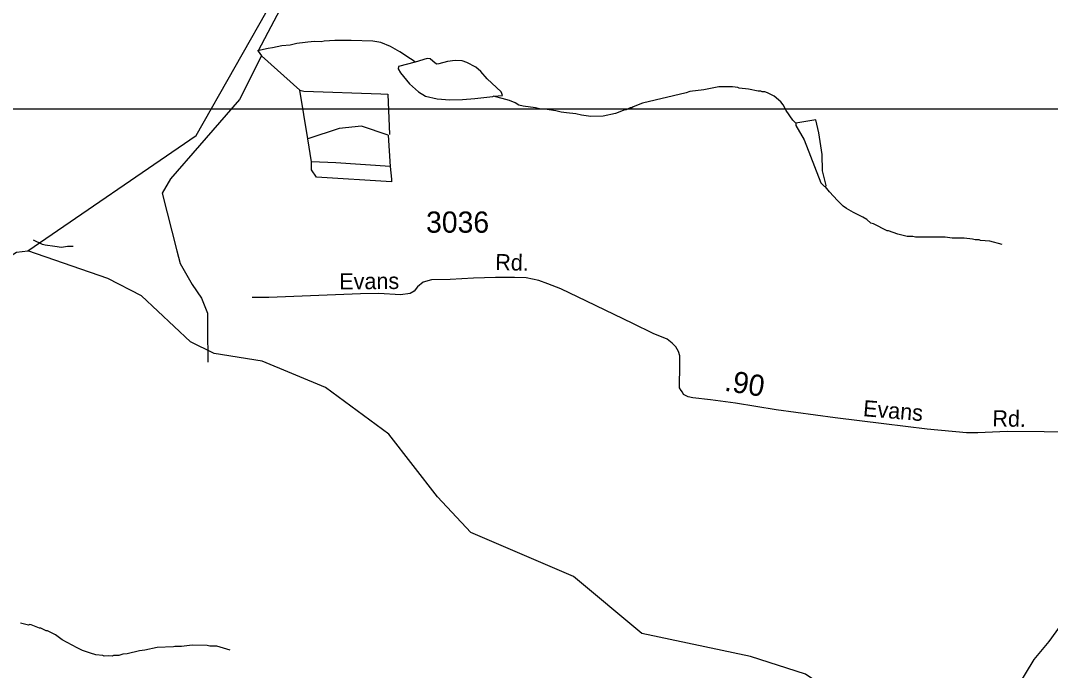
# Model space of a CAD drawing. Extents: x 1547597 to 1699558, y 810033 to 920809.
# Drawn here: x 1609618 to 1615688, y 827999 to 831828 of the extents above; entities that cross this region are included whole.
import ezdxf

# ---------------------------------------------------------------- set-up
doc = ezdxf.new("R2010")
doc.units = 0
for name, color, linetype in [('Exist Hydrographic Creek Single Shore', 7, 'Continuous'), ('Exist Hydrographic Misc Water Feature', 7, 'Continuous'), ('Exist Road Non-System Type 51', 7, 'Continuous'), ('Exist Road Secondary Mileage Hundredths English Label', 7, 'Continuous'), ('Exist Road Secondary Type 51 Attributed', 7, 'Continuous'), ('Exist Road Secondary Type 51 Label', 7, 'Continuous'), ('Exist Road Secondary Type 51 Number Label', 7, 'Continuous'), ('Map Preparation Inset Cut Line', 7, 'Continuous')]:
    doc.layers.add(name, color=color, linetype=linetype)

msp = doc.modelspace()

# ---------------------------------------------------------------- linework, layer by layer
at = {"layer": 'Exist Hydrographic Creek Single Shore'}
for points in [[(1609659.7, 830472.1), (1610651.7, 831151.1), (1611112.7, 831962.5), (1611121.7, 832011.5)], [(1606665.7, 828095.8), (1606891.9, 828225.7), (1607162.7, 828310.2), (1607833.6, 828602.7), (1608128.8, 828653.6), (1608244.3, 828846.1), (1608341, 828973.5), (1608539.5, 829644), (1608748.2, 829893.6), (1609155.7, 830193.4), (1609592.7, 830463.6), (1609659.7, 830472.1)], [(1614418.7, 827857.8), (1614244.7, 827976.2), (1613920.7, 828081.3), (1613280.7, 828215.7), (1612876.7, 828552.1), (1612271.7, 828810.6), (1612074.7, 829021.4), (1611787.7, 829391.6), (1611415.7, 829665), (1611042.6, 829820.4), (1610759.7, 829865.5), (1610619.7, 829934), (1610330.7, 830205.7), (1610132.7, 830308.2), (1609659.7, 830472.1)]]:
    msp.add_lwpolyline(points, dxfattribs=at)
at = {"layer": 'Exist Hydrographic Misc Water Feature'}
for points in [[(1611944.4, 831583), (1611932.6, 831592.1), (1611916.7, 831602.3), (1611853.3, 831643.2), (1611797.8, 831676), (1611742.1, 831698.7), (1611694.3, 831707.4), (1611566.5, 831711.2), (1611470.5, 831710.5), (1611406.4, 831707.4), (1611390.4, 831703.6), (1611350.4, 831704.2), (1611310.4, 831700.7), (1611294.3, 831698.9), (1611246.4, 831693.7), (1611206.2, 831682.2), (1611158.2, 831678.8), (1611102.1, 831667.7), (1611078, 831664), (1611015.1, 831649.2)], [(1611944.4, 831583), (1611845.6, 831557.3), (1611843.9, 831542.8), (1611856.5, 831521), (1611909.6, 831455.3), (1611962.9, 831408.8), (1612004.4, 831383.5), (1612074.2, 831367.4), (1612147.4, 831361), (1612222.8, 831362.6), (1612295.9, 831368.1), (1612401.6, 831381.2), (1612405.9, 831381.6)], [(1612405.9, 831381.6), (1612457.6, 831386.4), (1612455, 831397.8), (1612449.8, 831408.2), (1612368.7, 831484.7), (1612331.4, 831527.7), (1612300.3, 831552.9), (1612248.5, 831580.9), (1612220.4, 831590.1), (1612179.5, 831592.1), (1612133.6, 831587.8), (1612082.9, 831573.1), (1612070.9, 831571), (1612061.1, 831576.6), (1612031.7, 831603.4), (1612014.9, 831603.6), (1611944.4, 831583)], [(1614187.7, 831224.4), (1614170.4, 831241), (1614131.2, 831297.5), (1614113.7, 831331.7), (1614100, 831349.9), (1614060.5, 831382.4), (1614020.7, 831403), (1614004.8, 831407.3), (1613988.8, 831407.5), (1613980.9, 831411.6), (1613964.9, 831411.8), (1613909.1, 831424.6), (1613853.2, 831429.3), (1613845.3, 831433.4), (1613813.3, 831437.9), (1613733.3, 831437), (1613645.2, 831420.2), (1613563.1, 831409.4), (1613541, 831401.7), (1613284.4, 831341.3), (1613228.1, 831320.1), (1613220, 831314.2), (1613212, 831314.3), (1613187.9, 831302.6), (1613179.9, 831302.8), (1613123.6, 831279.6), (1613051.4, 831264.5), (1612979.5, 831263.6), (1612923.6, 831270.3), (1612891.7, 831278.8), (1612835.8, 831283.6), (1612803.9, 831288), (1612772.1, 831296.5), (1612708.2, 831305.3), (1612684.2, 831305.6), (1612652.3, 831314.1), (1612580.5, 831323.1), (1612555.1, 831330.5), (1612532.4, 831342.5), (1612499.5, 831357.7), (1612405.9, 831381.6)], [(1614362.3, 830848.6), (1614366, 830855.6), (1614345.4, 830942.6), (1614341.9, 831039.3), (1614322.6, 831166), (1614305.3, 831243), (1614187.7, 831224.4)], [(1614187.7, 831224.4), (1614188.5, 831209.1), (1614236.3, 831125.5), (1614335.6, 830871.3), (1614354.3, 830851.3), (1614362.3, 830848.6)], [(1615403.7, 830507.9), (1615332, 830528.9), (1615276.2, 830531.7), (1615268.2, 830535.8), (1615244.2, 830536.1), (1615228.3, 830540.3), (1615180.4, 830545), (1615108.4, 830546), (1615068.5, 830552.6), (1614892.6, 830551.1), (1614876.7, 830555.3), (1614844.7, 830555.7), (1614788.9, 830568.5), (1614733.3, 830589.2), (1614725.3, 830589.4), (1614645.8, 830630.5), (1614629.9, 830634.7), (1614606.2, 830655), (1614582.4, 830669.3), (1614526.8, 830696.1), (1614487.2, 830720.6), (1614467.3, 830734.9), (1614433.8, 830767.4), (1614386.5, 830818.6), (1614362.3, 830848.6)], [(1609928, 830497.2), (1609894, 830496.8), (1609858.8, 830491.3), (1609818.8, 830495.8), (1609763, 830504.6), (1609747, 830508.8), (1609694, 830533.9)], [(1610853.8, 828118), (1610774.1, 828141.1), (1610734.1, 828141.6), (1610718.3, 828145.8), (1610628.3, 828147.1), (1610566.2, 828140), (1610526.2, 828140.5), (1610518.2, 828136.6), (1610422.3, 828134), (1610350.1, 828117), (1610318, 828113.5), (1610245.8, 828096.4), (1610219.9, 828094.8), (1610197.7, 828087.1), (1610165.7, 828085.6), (1610157.6, 828081.7), (1610133.8, 828084), (1610109.8, 828082.3), (1610101.8, 828086.4), (1610061.9, 828091), (1610030, 828099.5), (1609982.2, 828116.1), (1609950.5, 828132.6), (1609863.2, 828179.7), (1609823.6, 828208.3), (1609775.9, 828230.9), (1609767.9, 828231), (1609736.2, 828247.5), (1609728.2, 828247.6), (1609680.5, 828266.3), (1609672.5, 828268.4), (1609664.5, 828264.5), (1609616.7, 828277.2)]]:
    msp.add_lwpolyline(points, dxfattribs=at)
at = {"layer": 'Exist Road Non-System Type 51'}
for points in [[(1611018.5, 831647.4), (1611077.3, 831759.8), (1611165.4, 831926.7), (1611263.9, 832063.2), (1611333.4, 832186.3), (1611388.8, 832303.4), (1611466.8, 832458.4), (1611526.4, 832585.6), (1611590, 832710.6), (1611630.5, 832781.4)], [(1611037, 831619.9), (1610907.3, 831363), (1610672.7, 831092.3), (1610501.5, 830896.1), (1610451.8, 830810.5)], [(1611018.5, 831647.4), (1611037, 831619.9)], [(1611037, 831619.9), (1611263.3, 831418.2), (1611288.2, 831412.7)], [(1611310.3, 831130.9), (1611263.3, 831418.2)], [(1611288.2, 831412.7), (1611740.9, 831396.1), (1611782.3, 831393.4)], [(1611782.3, 831393.4), (1611793.3, 831155.8)], [(1611785, 831153), (1611627.7, 831205.5), (1611495.2, 831191.7), (1611310.3, 831130.9)], [(1611332.3, 830995.6), (1611310.3, 831130.9)], [(1611785, 831153), (1611796.1, 830968)], [(1611796.1, 830968), (1611475.9, 830990.1), (1611332.3, 830995.6)], [(1611362.7, 830904.4), (1611332.3, 830948.6), (1611332.3, 830995.6)], [(1611796.1, 830968), (1611804.3, 830893.4), (1611804.3, 830876.8)], [(1611804.3, 830876.8), (1611362.7, 830904.4)], [(1610451.8, 830810.5), (1610538.1, 830471.8), (1610557.4, 830397.2), (1610629.2, 830272.9), (1610684.4, 830192.8), (1610720.3, 830104.4), (1610720.3, 830016)], [(1611621.1, 830216.8), (1611081.9, 830196.5), (1610981.8, 830195.7)], [(1610720.3, 830016), (1610720.7, 829815.9)]]:
    msp.add_lwpolyline(points, dxfattribs=at)
at = {"layer": 'Exist Road Secondary Type 51 Attributed'}
for points in [[(1615875.1, 829402.9), (1615651.8, 829403.9), (1615433.7, 829406), (1615261.1, 829397.7), (1615193.2, 829399.3), (1614962.3, 829419.3), (1614705.6, 829450.7), (1614420.2, 829486.1), (1614072.3, 829533.4), (1613832.1, 829572.9), (1613684.4, 829593), (1613580.1, 829605.8), (1613553.6, 829611.5), (1613526.4, 829624.3), (1613519.7, 829638.2), (1613511, 829648.5), (1613502.8, 829664.4), (1613501.2, 829696.8), (1613504.3, 829770.3), (1613503.5, 829852), (1613495.3, 829878.7), (1613479.4, 829905.4), (1613458.3, 829928), (1613430.1, 829950.6), (1613345.7, 829983.4), (1613226.8, 830043.6), (1612953.7, 830173.6), (1612801.9, 830247.1), (1612725.6, 830276.9), (1612673.2, 830295.4), (1612598.2, 830311.3), (1612528.8, 830314.9), (1612418.1, 830314.4), (1612287.1, 830310.3), (1612150.1, 830302.6), (1612040.2, 830299.5), (1611991.1, 830286.6), (1611957.2, 830258.9), (1611938.7, 830233.2), (1611915.1, 830218.8), (1611856.5, 830212.7), (1611729, 830218.8), (1611621.1, 830216.8)], [(1615872.1, 828613.9), (1615854.5, 828536.3), (1615829.8, 828455.1), (1615794.5, 828359.8), (1615745.1, 828261), (1615678.1, 828169.2), (1615589.9, 828063.3), (1615494.7, 827904.5), (1615427.7, 827798.6), (1615367.7, 827696.2), (1615311.3, 827618.6), (1615247.8, 827540.9), (1615180.8, 827445.6), (1615022.9, 827216.6), (1614915.3, 827052.5)]]:
    msp.add_lwpolyline(points, dxfattribs=at)
at = {"layer": 'Map Preparation Inset Cut Line'}
for points in [[(1633724, 874749.3), (1571208, 874749.3), (1571208, 831307.2), (1633724, 831307.2)], [(1575502.6, 831307.2), (1641328.6, 831307.2), (1641328.6, 811336.3), (1575502.6, 811336.3)]]:
    msp.add_lwpolyline(points, close=True, dxfattribs=at)

# ---------------------------------------------------------------- texts
at = {"layer": 'Exist Road Secondary Mileage Hundredths English Label'}
msp.add_text('.90', height=125, rotation=350.64702, dxfattribs=at).set_placement((1613762.4, 829647.8))
at = {"layer": 'Exist Road Secondary Type 51 Label'}
for s, rotation, p in [('Rd.', 358.66896, (1612414.8, 830358)), ('Evans', 0.46862, (1611496.7, 830243.6)), ('Evans', 355.14614, (1614581.4, 829497.3)), ('Rd.', 358.83774, (1615345.5, 829437.4))]:
    msp.add_text(s, height=95, rotation=rotation, dxfattribs=at).set_placement(p)
at = {"layer": 'Exist Road Secondary Type 51 Number Label'}
msp.add_text('3036', height=125, dxfattribs=at).set_placement((1612007.8, 830577.9))

doc.saveas('drawing.dxf')
